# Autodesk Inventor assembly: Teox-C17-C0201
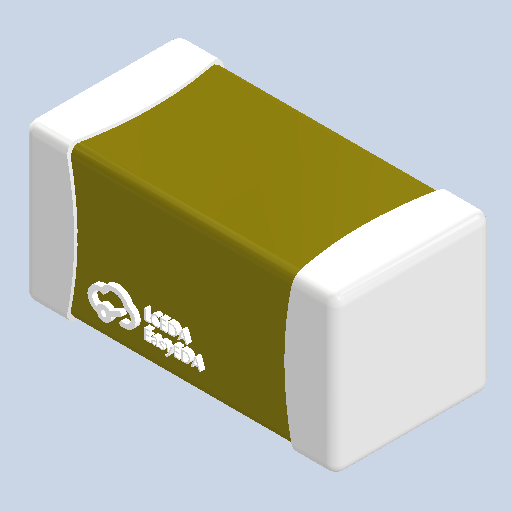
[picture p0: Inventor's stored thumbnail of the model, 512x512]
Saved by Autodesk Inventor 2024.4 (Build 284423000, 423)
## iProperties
Created: 2025-05
Part Number: Teox-C17-C0201
Document SubType Name: Assembly
Designer: AdminForWorker
Title: Teox-C17-C0201
Author: AdminForWorker
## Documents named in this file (2)
- c:\worker\convert-fusion-r02-cosv3\tmp\job-1\2\temp\files\be827049-a7f2-47ea-a815-8d9efd6bfce9\Teox-C17-C0201.iam
- c:\worker\convert-fusion-r02-cosv3\tmp\job-1\2\temp\files\be827049-a7f2-47ea-a815-8d9efd6bfce9\COMPOUND (3).ipt
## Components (1 placed, 1 different names)
1. COMPOUND (3):4
